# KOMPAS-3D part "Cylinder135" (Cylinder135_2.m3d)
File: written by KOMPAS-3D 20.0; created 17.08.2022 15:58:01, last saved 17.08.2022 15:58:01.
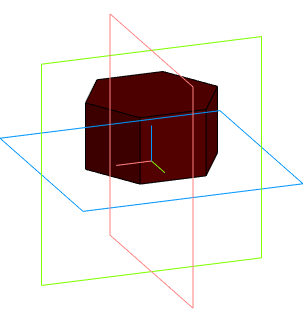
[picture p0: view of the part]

Document properties: Автор: artemsv220@gmail.com; Полное имя файла: \\192.168.2.25\новая общая папка\Медиа\Светильники\Кашпо\Кашпо и вазоны\DWG\Cylinder135_2.m3d

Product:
- Part/product: Cylinder135

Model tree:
1. Операция без истории:1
